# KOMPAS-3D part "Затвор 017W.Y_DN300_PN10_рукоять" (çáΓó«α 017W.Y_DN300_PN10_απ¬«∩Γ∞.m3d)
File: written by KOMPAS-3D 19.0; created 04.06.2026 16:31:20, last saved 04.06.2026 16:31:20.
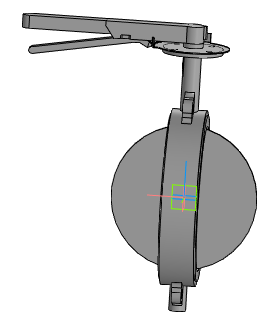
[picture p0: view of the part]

Document properties: Автор: Энергия; Полное имя файла: ..\..\..\3d для проектировщиков\017W разные\x.x Тип 017W.Y(S) Затвор дисковый поворотный межфланцевый\Затвор 017W.Y(S)_DN32-DN350_рукоять\Затвор 017W.Y_DN300_PN10_рукоять.a3d

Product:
- Part/product: Затвор 017W.Y_DN300_PN10_рукоять
    Масса: 31.6573

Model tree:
1. Операция без истории:1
